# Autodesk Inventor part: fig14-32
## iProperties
Created: 2005-03
Part Number: fig14-32
Document SubType Name: Sheet Metal
Designer: CADCIM
Manufacturer: Standard
Standards Organization: Custom
Author: CADCIM
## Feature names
1. Plate1
